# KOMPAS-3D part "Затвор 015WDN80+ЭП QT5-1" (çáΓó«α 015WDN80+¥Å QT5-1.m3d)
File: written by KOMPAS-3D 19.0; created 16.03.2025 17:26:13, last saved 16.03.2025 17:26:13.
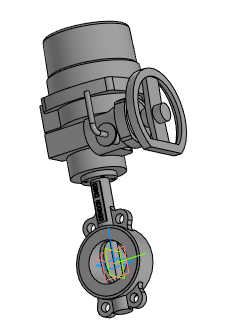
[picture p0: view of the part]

Document properties: Полное имя файла: Затвор 015WDN80+ЭП QT5-1.a3d

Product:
- Part/product: Затвор 015WDN80+ЭП QT5-1
    Масса: 44.8427

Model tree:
1. Операция без истории:1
